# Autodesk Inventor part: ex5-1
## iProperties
Created: 2006-03
Part Number: ex5-1
Document SubType Name: Modeling
Designer: Elise Moss
Density: 1 g/cm^3
Author: Elise Moss
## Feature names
1. Extrusion1
2. Extrusion2
3. Hole1
4. Fillet1
5. Hole2
6. Rectangular Pattern1
7. Fillet2
